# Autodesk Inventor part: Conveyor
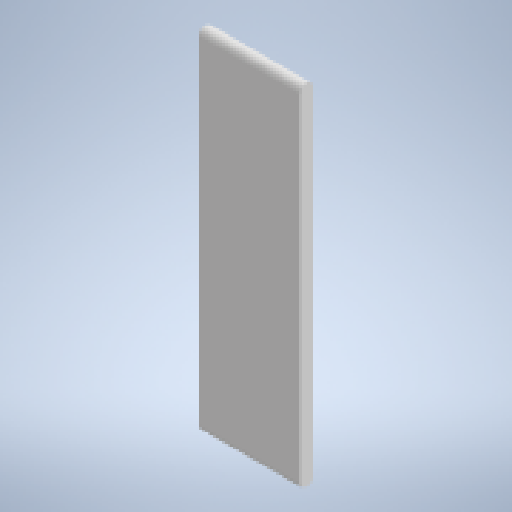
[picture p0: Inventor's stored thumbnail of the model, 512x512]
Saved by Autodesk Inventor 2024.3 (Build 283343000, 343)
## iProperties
Created: 2024-12
Part Number: Conveyor
Material: Generic
Document SubType Name: Modeling
Designer: ruhr
Density: 1 g/cm^3
Appearance: Default
Author: ruhr
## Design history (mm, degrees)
sketch "Sketch1"
  geometry: L1 (14.845, -38.837)-(-285.155, -38.837); L2 (-285.155, -38.837)-(-285.155, -26.837); L3 (-285.155, -26.837)-(14.845, -26.837); L4 (14.845, -26.837)-(14.845, -38.837); A1 r 6 centre (14.845, -32.837) between (14.845, -38.837) and (14.845, -26.837); A2 r 6 centre (-285.155, -32.837) between (-285.155, -26.837) and (-285.155, -38.837); 1 further point
  constraints: 8 end point, 4 point on circle, 2 centre point, 2 parallel, 2 tangent, 1 horizontal, 1 perpendicular
  dimensions: "d0" = 300 distance of L2.end L3.end; "d1" = 12 distance of L1.end L2.end
extrude "Extrusion1" new body sketch "Sketch1" distance "d2" = 90; taper "d3" = 0 deg
body "Solid1"
